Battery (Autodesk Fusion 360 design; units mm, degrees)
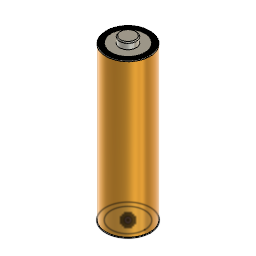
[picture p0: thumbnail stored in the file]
part number: 2025-09-17-21-21-37-963
sketch "Sketch1" plane through (0, 0, 0) normal (0, 0, 1) x axis (1, 0, 0)
  circle C1 centre (0, 0) radius 6.9
  circle C2 centre (0, 0) radius 5.25
  point P1 (0, 0)
  point P2 (0, 0)
  point P3 (0, 0)
  coincident P1 P2
  coincident P1 P3
  dimension "d1" diameter C1 = 13.8
  dimension "d2" diameter C2 = 10.5
extrude "Extrude1" new body sketch "Sketch1" along normal blind 48
extrude "Extrude2" add sketch "Sketch1" profile of C2 against normal blind 0.1
sketch "Sketch2" plane through (0, 0, 48) normal (0, 0, 1) x axis (-1, 0, 0)
  circle C1 centre (0, 0) radius 6.9
  circle C2 centre (0, 0) radius 5.25
  circle C3 centre (0, 0) radius 2.6
  point P1 (0, 0)
  point P3 (0, 0)
  point P4 (0, 0)
  coincident P1 P3
  coincident P1 P4
  dimension "d7" diameter C2 = 10.5
  dimension "d8" diameter C3 = 5.2
extrude "Extrude3" cut sketch "Sketch2" profile of C2 C3 against normal blind 0.01
extrude "Extrude4" add of existing geometry blind 2
fillet "Fillet1" radius 0.3 0.2 0.2
fillet "Fillet2" radius 0.01
sketch "Sketch3" plane through (0, 0, -0.1) normal (0, 0, -1) x axis (1, 0, 0)
  circle C1 centre (0, 0) radius 5.25
move "Move1" RotateAngle 30
move "Move2" RotateAngle 90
